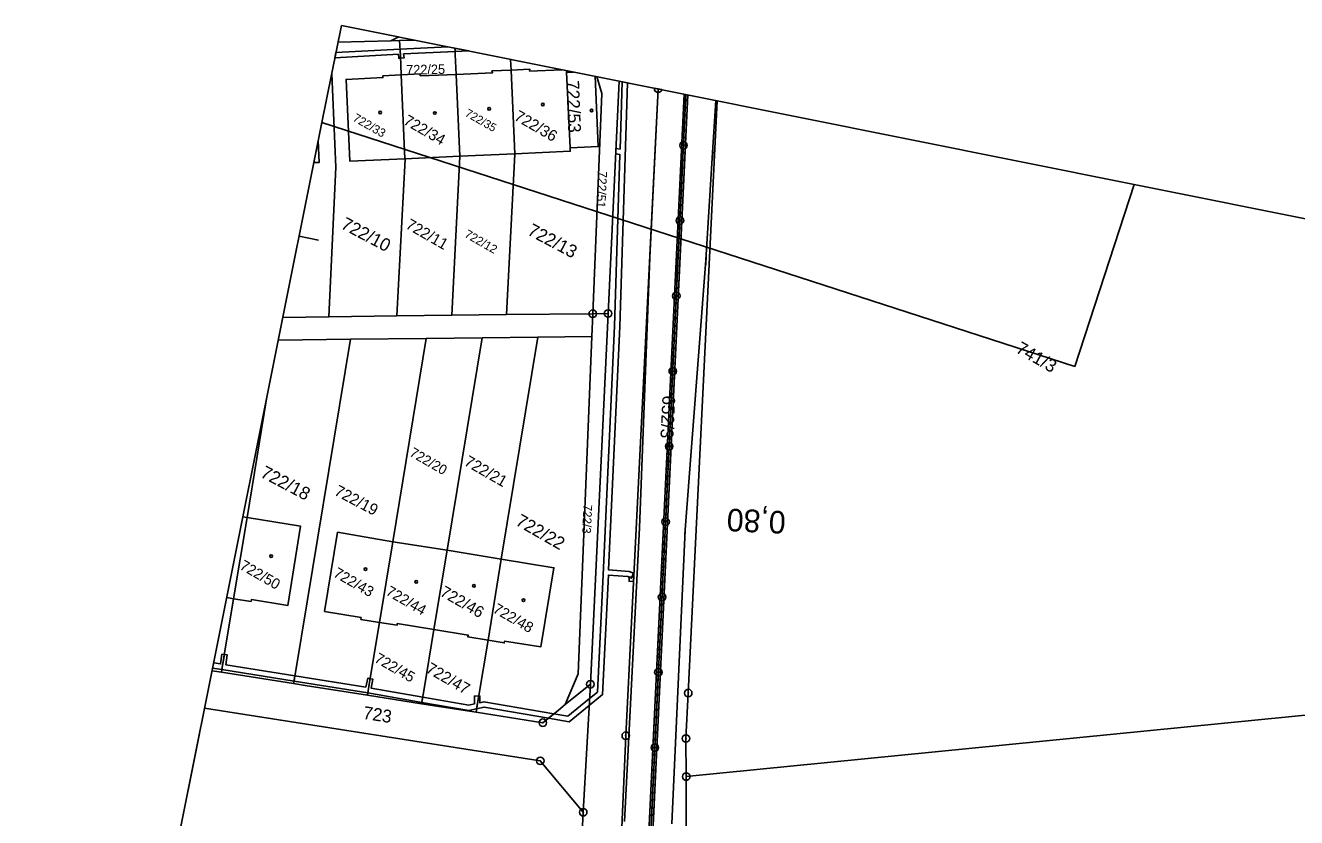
# Model space of a CAD drawing. Extents: x -548552 to -543113, y -1131925 to -1123599.
# Drawn here: x -548348.8 to -548180.1, y -1131041.8 to -1130936.7 of the extents above; entities that cross this region are included whole.
import ezdxf

# ---------------------------------------------------------------- set-up
doc = ezdxf.new("R2010")
doc.units = 0
for name, color, linetype in [('Hranice parcel', 7, 'Continuous'), ('Parcelní čísla', 7, 'Continuous'), ('Profile', 7, 'Continuous'), ('PROFILY NÁVRH', 7, 'Continuous'), ('STANIČENÍ', 7, 'Continuous'), ('SVAHY', 7, 'Continuous'), ('Vnitřní kresba', 7, 'Continuous'), ('Věcná břemena k části', 7, 'Continuous'), ('Značky bodu BP', 7, 'Continuous'), ('Značky budov', 7, 'Continuous')]:
    doc.layers.add(name, color=color, linetype=linetype)

msp = doc.modelspace()

# ---------------------------------------------------------------- linework, layer by layer
at = {"layer": 'Hranice parcel'}
for p, q in [((-548299.15, -1130938.65), (-548297.22, -1130938.6)), ((-548298.94, -1130943.21), (-548298.45, -1130954.35)), ((-548291.15, -1130954.01), (-548291.65, -1130943.16)), ((-548284.36, -1130942.59), (-548283.85, -1130953.69)), ((-548276.99, -1130942.88), (-548276.07, -1130942.84)), ((-548276.53, -1130952.88), (-548276.99, -1130942.88)), ((-548270.02, -1130944.05), (-548271.49, -1130974.88)), ((-548291.15, -1130954.01), (-548298.45, -1130954.35)), ((-548283.85, -1130953.69), (-548291.15, -1130954.01)), ((-548314.65, -1130975.4), (-548308.54, -1130975.33)), ((-548308.54, -1130975.33), (-548299.52, -1130975.19)), ((-548299.52, -1130975.19), (-548292.24, -1130975.11)), ((-548292.24, -1130975.11), (-548284.95, -1130975.03)), ((-548284.95, -1130975.03), (-548273.52, -1130974.91)), ((-548273.83, -1131024.08), (-548271.49, -1130974.88)), ((-548273.52, -1130974.91), (-548273.65, -1130977.95)), ((-548271.49, -1130974.88), (-548273.52, -1130974.91)), ((-548273.65, -1130977.95), (-548280.8, -1130978.03)), ((-548305.67, -1130978.3), (-548315.25, -1130978.4)), ((-548295.63, -1130978.19), (-548305.67, -1130978.3)), ((-548300.07, -1131005.16), (-548295.63, -1130978.19)), ((-548288.21, -1130978.1), (-548295.63, -1130978.19)), ((-548292.86, -1131006.29), (-548288.21, -1130978.1)), ((-548280.8, -1130978.03), (-548288.21, -1130978.1)), ((-548285.66, -1131007.47), (-548280.8, -1130978.03)), ((-548319.41, -1131001.95), (-548316.81, -1130986.19)), ((-548319.41, -1131001.95), (-548321.2, -1131012.73)), ((-548300.07, -1131005.16), (-548301.84, -1131015.88)), ((-548300.07, -1131005.16), (-548292.86, -1131006.29)), ((-548294.6, -1131016.82), (-548292.86, -1131006.29)), ((-548292.86, -1131006.29), (-548285.66, -1131007.47)), ((-548285.66, -1131007.47), (-548287.42, -1131018.23)), ((-548322.8, -1131022.48), (-548324.05, -1131022.28)), ((-548313.22, -1131023.98), (-548322.8, -1131022.48)), ((-548277.17, -1131026.78), (-548273.83, -1131024.08)), ((-548274.79, -1131041.06), (-548273.83, -1131024.08)), ((-548296.23, -1131026.66), (-548303.44, -1131025.52)), ((-548289, -1131027.79), (-548296.23, -1131026.66)), ((-548261.12, -1131036.32), (-548173.67, -1131027.67)), ((-548275.88, -1131062.79), (-548274.79, -1131041.06))]:
    msp.add_line(p, q, dxfattribs=at)
for points in [[(-548307.33, -1130938.88), (-548300.34, -1130938.69), (-548299.15, -1130938.65)], [(-548298.94, -1130943.21), (-548299.06, -1130940.7), (-548299.15, -1130938.65)], [(-548291.65, -1130943.16), (-548291.77, -1130940.51), (-548291.8, -1130939.68)], [(-548284.36, -1130942.59), (-548284.43, -1130941.16)], [(-548277.61, -1130942.53), (-548281.91, -1130942.71), (-548281.88, -1130942.46), (-548284.36, -1130942.59)], [(-548308.17, -1130943.09), (-548307.61, -1130955.45), (-548308.54, -1130975.33)], [(-548298.45, -1130954.35), (-548305.76, -1130954.68), (-548306.25, -1130943.83), (-548301.38, -1130943.58), (-548301.38, -1130943.33), (-548298.94, -1130943.21)], [(-548298.94, -1130943.21), (-548296.42, -1130943.09), (-548296.41, -1130943.33), (-548291.65, -1130943.16)], [(-548291.65, -1130943.16), (-548286.82, -1130942.94), (-548286.9, -1130942.7), (-548284.36, -1130942.59)], [(-548276.99, -1130942.88), (-548277, -1130942.65)], [(-548273.19, -1130943.41), (-548272.79, -1130952.71), (-548276.53, -1130952.88)], [(-548273.52, -1130974.91), (-548272.32, -1130945.68), (-548272.99, -1130943.45)], [(-548264.85, -1130945.08), (-548269.14, -1131030.91), (-548269.98, -1131050.17), (-548279.48, -1131235), (-548279.89, -1131244)], [(-548261.12, -1131036.32), (-548261.15, -1131031.27), (-548260.85, -1131025.24), (-548257.02, -1130946.66)], [(-548309.95, -1130951.96), (-548309.83, -1130954.83), (-548310.53, -1130954.86)], [(-548299.52, -1130975.19), (-548298.44, -1130954.4), (-548298.45, -1130954.35)], [(-548292.24, -1130975.11), (-548291.15, -1130954.07), (-548291.15, -1130954.01)], [(-548284.95, -1130975.03), (-548283.85, -1130953.75), (-548283.85, -1130953.69)], [(-548276.53, -1130952.88), (-548276.51, -1130953.36), (-548283.85, -1130953.69)], [(-548273.65, -1130977.95), (-548275.48, -1131022.68), (-548277.17, -1131026.78)], [(-548313.22, -1131023.98), (-548312.89, -1131022), (-548305.67, -1130978.3)], [(-548319.41, -1131001.95), (-548312.29, -1131003.11), (-548314, -1131013.63), (-548318.82, -1131012.84), (-548318.86, -1131013.09), (-548321.2, -1131012.73)], [(-548319.95, -1131001.86), (-548319.41, -1131001.95)], [(-548301.84, -1131015.88), (-548304.3, -1131015.47), (-548304.27, -1131015.23), (-548309.11, -1131014.42), (-548307.4, -1131003.91), (-548300.07, -1131005.16)], [(-548285.66, -1131007.47), (-548278.68, -1131008.61), (-548280.4, -1131019.11), (-548285.22, -1131018.34), (-548285.27, -1131018.58), (-548287.42, -1131018.23)], [(-548322.8, -1131022.48), (-548322.47, -1131020.49), (-548321.2, -1131012.73)], [(-548321.2, -1131012.73), (-548322.1, -1131012.57)], [(-548303.44, -1131025.52), (-548303.11, -1131023.54), (-548301.84, -1131015.88)], [(-548301.84, -1131015.88), (-548299.5, -1131016.25), (-548299.46, -1131016.03), (-548294.6, -1131016.82)], [(-548296.23, -1131026.66), (-548295.9, -1131024.69), (-548294.6, -1131016.82)], [(-548294.6, -1131016.82), (-548290.05, -1131017.56), (-548290.08, -1131017.8), (-548287.42, -1131018.23)], [(-548287.42, -1131018.23), (-548288.68, -1131025.83), (-548289, -1131027.79)], [(-548303.44, -1131025.52), (-548311.69, -1131024.23), (-548313.22, -1131023.98)], [(-548277.17, -1131026.78), (-548278.07, -1131027.5), (-548280.15, -1131029.18), (-548289, -1131027.79)], [(-548325.04, -1131027.23), (-548280.48, -1131034.24), (-548274.79, -1131041.06)], [(-548262.3, -1131075.09), (-548261.13, -1131050.62), (-548261.12, -1131036.32)]]:
    msp.add_lwpolyline(points, dxfattribs=at)
at = {"layer": 'Profile'}
for p, q in [((-548306.88, -1130936.66), (-548201.68, -1130957.75)), ((-548309.46, -1130949.53), (-548348.82, -1131145.88)), ((-548309.46, -1130949.53), (-548209.52, -1130981.93)), ((-548201.68, -1130957.75), (-548209.52, -1130981.93)), ((-548201.68, -1130957.75), (-548161.28, -1130965.85)), ((-548309.9, -1130965.16), (-548312.49, -1130964.64)), ((-548325.71, -1131030.6), (-548348.82, -1131145.88))]:
    msp.add_line(p, q, dxfattribs=at)
at = {"layer": 'PROFILY NÁVRH'}
for p, q in [((-548276, -1131252.52), (-548261.4, -1130945.78)), ((-548275.5, -1131252.55), (-548260.91, -1130945.87)), ((-548264.85, -1130945.09), (-548265.23, -1130953.15)), ((-548257.2, -1130946.62), (-548257.61, -1130953.52)), ((-548265.23, -1130953.15), (-548265.96, -1130967.46)), ((-548257.61, -1130953.52), (-548258.5, -1130967.81)), ((-548265.96, -1130967.46), (-548267.33, -1131003.3)), ((-548258.5, -1130967.81), (-548261.25, -1131003.59)), ((-548267.33, -1131003.3), (-548269.29, -1131042.28)), ((-548261.25, -1131003.59), (-548263.02, -1131042.58))]:
    msp.add_line(p, q, dxfattribs=at)
at = {"layer": 'STANIČENÍ'}
for p, q in [((-548275.75, -1131252.54), (-548261.16, -1130945.83)), ((-548257.64, -1130954.25), (-548257.59, -1130953.05)), ((-548258.53, -1130968.43), (-548258.47, -1130967.17)), ((-548267.33, -1131003.48), (-548267.32, -1131003.11)), ((-548261.28, -1131004.21), (-548261.22, -1131002.99))]:
    msp.add_line(p, q, dxfattribs=at)
for centre, radius in [((-548261.24, -1130947.55), 0.1), ((-548261.19, -1130946.55), 0.1), ((-548261.29, -1130948.55), 0.1), ((-548261.38, -1130950.54), 0.1), ((-548261.33, -1130949.54), 0.1), ((-548261.48, -1130952.57), 0.5), ((-548261.48, -1130952.54), 0.1), ((-548261.43, -1130951.54), 0.1), ((-548261.52, -1130953.54), 0.1), ((-548261.62, -1130955.54), 0.1), ((-548261.57, -1130954.54), 0.1), ((-548261.71, -1130957.54), 0.1), ((-548261.67, -1130956.54), 0.1), ((-548261.81, -1130959.53), 0.1), ((-548261.76, -1130958.54), 0.1), ((-548261.86, -1130960.53), 0.1), ((-548261.95, -1130962.56), 0.5), ((-548261.95, -1130962.53), 0.1), ((-548261.9, -1130961.53), 0.1), ((-548262.05, -1130964.53), 0.1), ((-548262, -1130963.53), 0.1), ((-548262.09, -1130965.53), 0.1), ((-548262.19, -1130967.53), 0.1), ((-548262.14, -1130966.53), 0.1), ((-548262.28, -1130969.52), 0.1), ((-548262.24, -1130968.52), 0.1), ((-548262.33, -1130970.52), 0.1), ((-548262.43, -1130972.55), 0.5), ((-548262.43, -1130972.52), 0.1), ((-548262.38, -1130971.52), 0.1), ((-548262.52, -1130974.52), 0.1), ((-548262.47, -1130973.52), 0.1), ((-548262.57, -1130975.52), 0.1), ((-548262.66, -1130977.51), 0.1), ((-548262.62, -1130976.52), 0.1), ((-548262.76, -1130979.51), 0.1), ((-548262.71, -1130978.51), 0.1), ((-548262.81, -1130980.51), 0.1), ((-548262.9, -1130982.54), 0.5), ((-548262.9, -1130982.51), 0.1), ((-548262.86, -1130981.51), 0.1), ((-548263, -1130984.51), 0.1), ((-548262.95, -1130983.51), 0.1), ((-548263.09, -1130986.51), 0.1), ((-548263.05, -1130985.51), 0.1), ((-548263.14, -1130987.5), 0.1), ((-548263.24, -1130989.5), 0.1), ((-548263.19, -1130988.5), 0.1), ((-548263.33, -1130991.5), 0.1), ((-548263.28, -1130990.5), 0.1), ((-548263.38, -1130992.52), 0.5), ((-548263.38, -1130992.5), 0.1), ((-548263.47, -1130994.5), 0.1), ((-548263.43, -1130993.5), 0.1), ((-548263.57, -1130996.49), 0.1), ((-548263.52, -1130995.5), 0.1), ((-548263.62, -1130997.49), 0.1), ((-548263.71, -1130999.49), 0.1), ((-548263.66, -1130998.49), 0.1), ((-548263.81, -1131001.49), 0.1), ((-548263.76, -1131000.49), 0.1), ((-548263.85, -1131002.51), 0.5), ((-548263.85, -1131002.49), 0.1), ((-548263.95, -1131004.49), 0.1), ((-548263.9, -1131003.49), 0.1), ((-548264.04, -1131006.48), 0.1), ((-548264.04, -1131006.51), 0.1), ((-548264, -1131005.48), 0.1), ((-548264.09, -1131007.48), 0.1), ((-548264.09, -1131007.51), 0.1), ((-548264.19, -1131009.48), 0.1), ((-548264.14, -1131008.48), 0.1), ((-548264.28, -1131011.48), 0.1), ((-548264.23, -1131010.48), 0.1), ((-548264.33, -1131012.5), 0.5), ((-548264.38, -1131013.48), 0.1), ((-548264.33, -1131012.48), 0.1), ((-548264.42, -1131014.47), 0.1), ((-548264.52, -1131016.47), 0.1), ((-548264.47, -1131015.47), 0.1), ((-548264.61, -1131018.47), 0.1), ((-548264.57, -1131017.47), 0.1), ((-548264.66, -1131019.47), 0.1), ((-548264.76, -1131021.47), 0.1), ((-548264.71, -1131020.47), 0.1), ((-548264.81, -1131022.49), 0.5), ((-548264.85, -1131023.47), 0.1), ((-548264.8, -1131022.47), 0.1), ((-548264.9, -1131024.46), 0.1), ((-548264.99, -1131026.46), 0.1), ((-548264.95, -1131025.46), 0.1), ((-548265.09, -1131028.46), 0.1), ((-548265.04, -1131027.46), 0.1), ((-548265.14, -1131029.46), 0.1), ((-548265.28, -1131032.48), 0.5), ((-548265.23, -1131031.46), 0.1), ((-548265.18, -1131030.46), 0.1), ((-548265.33, -1131033.45), 0.1), ((-548265.28, -1131032.46), 0.1), ((-548265.42, -1131035.45), 0.1), ((-548265.37, -1131034.45), 0.1), ((-548265.47, -1131036.45), 0.1), ((-548265.56, -1131038.45), 0.1), ((-548265.52, -1131037.45), 0.1), ((-548265.66, -1131040.45), 0.1), ((-548265.61, -1131039.45), 0.1), ((-548265.71, -1131041.45), 0.1)]:
    msp.add_circle(centre, radius, dxfattribs=at)
at = {"layer": 'SVAHY'}
msp.add_line((-548306.88, -1130936.66), (-548309.46, -1130949.53), dxfattribs=at)
at = {"layer": 'Vnitřní kresba'}
msp.add_line((-548299.25, -1130938.19), (-548300.34, -1130938.69), dxfattribs=at)
at = {"layer": 'Věcná břemena k části'}
for p, q in [((-548307.61, -1130940.27), (-548307.75, -1130940.98)), ((-548291.81, -1130939.68), (-548292.77, -1130939.49)), ((-548289.95, -1130940.05), (-548291.81, -1130939.68)), ((-548268.9, -1130944.27), (-548269.6, -1130944.13)), ((-548323.83, -1131021.23), (-548323.97, -1131021.92))]:
    msp.add_line(p, q, dxfattribs=at)
for points in [[(-548307.75, -1130940.98), (-548299.32, -1130940.49), (-548299.28, -1130941.02), (-548299.04, -1130941.01), (-548299.06, -1130940.7), (-548299.1, -1130939.79), (-548307.61, -1130940.27)], [(-548292.77, -1130939.49), (-548299.1, -1130939.79), (-548299.06, -1130940.7), (-548299.04, -1130941.01), (-548298.57, -1130940.98), (-548298.62, -1130940.45), (-548291.79, -1130940.14), (-548291.81, -1130939.68)], [(-548291.81, -1130939.68), (-548291.79, -1130940.14), (-548289.95, -1130940.05)], [(-548269.6, -1130944.13), (-548269.89, -1130953.07), (-548270.44, -1130952.99), (-548270.47, -1130953.69), (-548269.91, -1130953.77), (-548270.65, -1130976.56), (-548272.14, -1131009.54), (-548272.89, -1131025.11), (-548273.94, -1131025.96), (-548276.84, -1131028.31), (-548278.68, -1131028), (-548279.4, -1131028.58), (-548276.64, -1131029.05), (-548273.99, -1131026.89), (-548272.21, -1131025.45), (-548271.44, -1131009.59), (-548268.85, -1131009.8), (-548268.36, -1131010), (-548268.1, -1131009.34), (-548268.69, -1131009.1), (-548271.41, -1131008.9), (-548269.95, -1130976.59), (-548268.9, -1130944.27)], [(-548323.97, -1131021.92), (-548322.74, -1131022.11), (-548322.47, -1131020.49), (-548322.42, -1131020.13), (-548322.73, -1131020.09), (-548322.92, -1131021.37), (-548323.83, -1131021.23)]]:
    msp.add_lwpolyline(points, dxfattribs=at)
for points in [[(-548268.68, -1131009.82), (-548268.7, -1131010.41), (-548268.12, -1131010.45), (-548268.08, -1131009.85)], [(-548322.74, -1131022.11), (-548313.16, -1131023.65), (-548313.05, -1131022.95), (-548322.23, -1131021.48), (-548322.04, -1131020.19), (-548322.42, -1131020.13)], [(-548313.16, -1131023.65), (-548303.38, -1131025.21), (-548303.11, -1131023.54), (-548303.07, -1131023.34), (-548303.38, -1131023.27), (-548303.64, -1131024.46), (-548313.05, -1131022.95)], [(-548303.38, -1131025.21), (-548296.19, -1131026.48), (-548296.08, -1131025.78), (-548302.95, -1131024.58), (-548302.69, -1131023.42), (-548303.07, -1131023.34), (-548303.11, -1131023.54)], [(-548296.19, -1131026.48), (-548289.97, -1131027.58), (-548288.93, -1131027.34), (-548288.68, -1131025.83), (-548288.65, -1131025.64), (-548289.21, -1131025.63), (-548289.22, -1131026.68), (-548289.99, -1131026.85), (-548296.08, -1131025.78)], [(-548288.68, -1131025.83), (-548288.93, -1131027.34), (-548287.94, -1131027.1), (-548279.4, -1131028.58), (-548278.68, -1131028), (-548287.97, -1131026.4), (-548288.52, -1131026.52), (-548288.5, -1131025.64), (-548288.65, -1131025.64)]]:
    msp.add_lwpolyline(points, close=True, dxfattribs=at)
at = {"layer": 'Značky bodu BP'}
for p, q in [((-548264.36, -1130945.18), (-548265.34, -1130944.99)), ((-548264.83, -1130945.09), (-548264.88, -1130945.08))]:
    msp.add_line(p, q, dxfattribs=at)
for centre, radius in [((-548273.52, -1130974.91), 0.5), ((-548271.49, -1130974.88), 0.5), ((-548273.52, -1130974.91), 0.0303), ((-548271.49, -1130974.88), 0.0303), ((-548273.83, -1131024.08), 0.5), ((-548273.83, -1131024.08), 0.0303), ((-548260.85, -1131025.24), 0.5), ((-548260.85, -1131025.24), 0.0303), ((-548280.15, -1131029.18), 0.5), ((-548280.15, -1131029.18), 0.0303), ((-548269.14, -1131030.91), 0.5), ((-548269.14, -1131030.91), 0.0303), ((-548261.15, -1131031.27), 0.5), ((-548261.15, -1131031.27), 0.0303), ((-548280.48, -1131034.24), 0.5), ((-548280.48, -1131034.24), 0.0303), ((-548261.12, -1131036.32), 0.5), ((-548261.12, -1131036.32), 0.0303), ((-548274.79, -1131041.06), 0.5), ((-548274.79, -1131041.06), 0.0303)]:
    msp.add_circle(centre, radius, dxfattribs=at)
for radius, start, end in [(0.5, 170.859, 346.4718), (0.0303, 207.8349, 309.4959)]:
    msp.add_arc((-548264.85, -1130945.07), radius, start, end, dxfattribs=at)
at = {"layer": 'Značky budov'}
for centre in [(-548287.28, -1130947.72), (-548280.14, -1130947.15), (-548301.73, -1130948.22), (-548294.48, -1130948.28), (-548273.67, -1130947.95), (-548316.21, -1131007.07), (-548303.69, -1131008.8), (-548296.94, -1131010.49), (-548289.29, -1131011.02), (-548282.72, -1131012.93)]:
    msp.add_circle(centre, 0.175, dxfattribs=at)

# ---------------------------------------------------------------- texts
at = {"layer": 'Parcelní čísla'}
for s, height, rotation, p in [('722/25', 1.262, 1.1814, (-548298.27, -1130943.19)), ('722/53', 1.7, 272.1814, (-548277.04, -1130943.97)), ('722/33', 1.139, 330.1814, (-548305.47, -1130949.26)), ('722/34', 1.445, 330.1814, (-548298.75, -1130949.68)), ('722/35', 1.09, 330.1814, (-548290.57, -1130948.62)), ('722/36', 1.487, 330.1814, (-548284.06, -1130949.12)), ('722/51', 1.2, 267.1814, (-548272.81, -1130955.96)), ('722/10', 1.7, 332.1814, (-548307.08, -1130963.52)), ('722/11', 1.47, 330.1814, (-548298.47, -1130963.5)), ('722/12', 1.139, 330.1814, (-548290.65, -1130964.68)), ('722/13', 1.7, 332.1814, (-548282.32, -1130964.36)), ('741/3', 1.7, 330.1814, (-548217.51, -1130979.98)), ('652/3', 1.7, 267.1814, (-548264.26, -1130985.73)), ('722/20', 1.3, 330.1814, (-548297.95, -1130993.71)), ('722/21', 1.491, 330.1814, (-548290.71, -1130994.93)), ('722/18', 1.7, 332.1814, (-548317.75, -1130996.5)), ('722/19', 1.5, 332.1814, (-548307.95, -1130998.89)), ('722/22', 1.7, 330.1814, (-548283.89, -1131002.87)), ('722/3', 1.149, 267.1814, (-548274.74, -1131000.21)), ('722/50', 1.4, 330.1814, (-548320.49, -1131008.72)), ('722/43', 1.4, 330.1814, (-548308.06, -1131009.71)), ('722/44', 1.4, 330.1814, (-548301.1, -1131012.14)), ('722/46', 1.518, 330.1814, (-548293.91, -1131012.25)), ('722/48', 1.4, 330.1814, (-548286.88, -1131014.47)), ('722/45', 1.4, 330.1814, (-548302.61, -1131021.04)), ('722/47', 1.518, 330.1814, (-548295.78, -1131022.41)), ('723', 1.7, 351.1814, (-548304.09, -1131028.65))]:
    msp.add_text(s, height=height, rotation=rotation, dxfattribs=at).set_placement(p)
at = {"layer": 'STANIČENÍ'}
msp.add_text('0,80', height=3, rotation=177.2755, dxfattribs=at).set_placement((-548247.85, -1131001.12))

doc.saveas('drawing.dxf')
